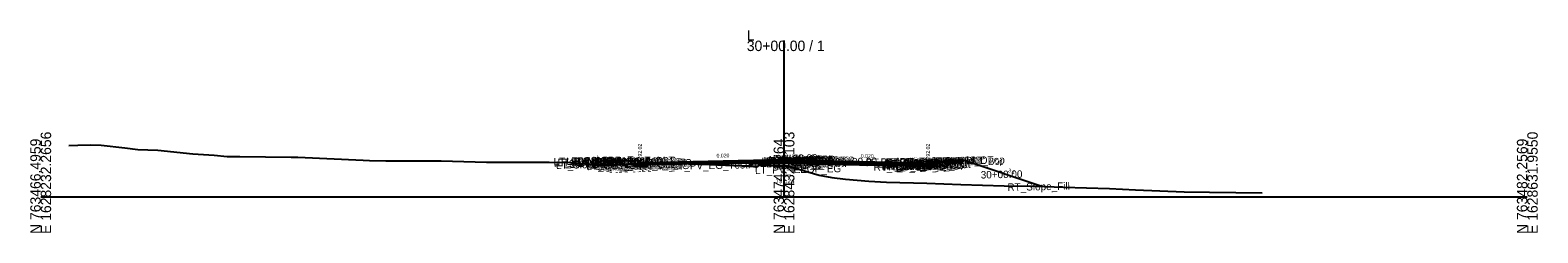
# Model space of a CAD drawing. Extents: x -26 to 4403, y -510 to 9556.
# Drawn here: x 1997.2 to 2402.8, y -9.7 to 44.7 of the extents above; entities that cross this region are included whole.
import ezdxf

# ---------------------------------------------------------------- set-up
doc = ezdxf.new("R2010")
doc.units = 0
for name, color, linetype in [('Default', 7, 'Continuous'), ('Exist CMT Pavement', 7, 'Continuous'), ('Exist Cross Section Cell', 7, 'Continuous'), ('Exist XS Center Line Elevation Label', 7, 'Continuous'), ('Exist XS Ground Line', 7, 'Continuous'), ('Prop CMT Conc Surface', 7, 'Continuous'), ('Prop CMT Concrete Structures', 7, 'Continuous'), ('Prop CMT Pvmt Course 1', 7, 'Continuous'), ('Prop CMT Pvmt Course 1 CG', 7, 'Continuous'), ('Prop CMT Pvmt Course 1 Wedge', 7, 'Continuous'), ('Prop CMT Pvmt Course 2', 7, 'Continuous'), ('Prop CMT Pvmt Course 2 Wedge', 7, 'Continuous'), ('Prop CMT Pvmt Course 3', 7, 'Continuous'), ('Prop CMT Pvmt Course 3 Wedge', 7, 'Continuous'), ('Prop CMT Pvmt Surface', 7, 'Continuous'), ('Prop CMT Pvmt Wedge Surface 1', 7, 'Continuous'), ('Prop CMT Pvmt Wedge Surface 2', 7, 'Continuous'), ('Prop CMT Pvmt Wedge Surface 3', 7, 'Continuous'), ('Prop CMT Slope Grass', 7, 'Continuous'), ('Prop CMT Subgrade Earthwork', 7, 'Continuous'), ('Prop XS Hydro Elevations', 7, 'Continuous'), ('Prop XS SE Text', 7, 'Continuous'), ('Prop XS Side Slope Text', 7, 'Continuous'), ('Scratch_Level_0', 7, 'Continuous')]:
    doc.layers.add(name, color=color, linetype=linetype)

msp = doc.modelspace()

# ---------------------------------------------------------------- linework, layer by layer
at = {"layer": 'Exist CMT Pavement'}
msp.add_lwpolyline([(2163.27, 8.89), (2165.6, 8.9), (2171.45, 8.94), (2179.91, 8.63), (2190.78, 8.23)], dxfattribs=at)
at = {"layer": 'Exist Cross Section Cell'}
for p, q in [((2200, 0), (2200, 41.94)), ((2000, 0), (2200, 0)), ((2200, 0), (2400, 0))]:
    msp.add_line(p, q, dxfattribs=at)
at = {"layer": 'Exist XS Ground Line'}
msp.add_lwpolyline([(2007.54, 13.74), (2010, 13.87), (2013.27, 13.98), (2016.24, 13.83), (2022.59, 13.11), (2026.12, 12.73), (2028.83, 12.63), (2031.47, 12.5), (2040.91, 11.51), (2046.71, 11.14), (2050.14, 10.82), (2053.55, 10.82), (2067.42, 10.65), (2068.48, 10.61), (2069.17, 10.63), (2086.73, 9.82), (2088.47, 9.74), (2092.85, 9.65), (2107.79, 9.66), (2119.91, 9.32), (2127.57, 9.28), (2136.85, 9.3), (2142.39, 9.21), (2146.29, 8.83), (2149.18, 8.58), (2149.55, 8.52), (2150.04, 8.48), (2156.17, 8.69), (2160.96, 8.87), (2165.6, 8.9), (2171.45, 8.94), (2179.91, 8.63), (2190.78, 8.23), (2192.8, 8.06), (2193.33, 8.48), (2198.8, 8.26), (2200, 8.24), (2201.17, 8.22), (2204.26, 7.3), (2209.45, 5.8), (2212.85, 5.2), (2216.58, 4.7), (2222.81, 4.21), (2227.54, 3.95), (2238.45, 3.61), (2247.56, 3.26), (2259.28, 2.96), (2267.57, 2.81), (2275.23, 2.58), (2287.59, 2.19), (2294.54, 1.89), (2307.66, 1.3), (2314.51, 1.2), (2328.67, 1.08)], dxfattribs=at)
at = {"layer": 'Prop CMT Conc Surface'}
for points in [[(2156.75, 9.61), (2151.75, 9.71)], [(2161.25, 9.02), (2161.25, 9.52), (2160.75, 9.52)], [(2163.25, 9.14), (2161.25, 9.02)], [(2236.75, 9.14), (2238.75, 9.02)], [(2238.75, 9.02), (2238.75, 9.52), (2239.25, 9.52)], [(2243.25, 9.61), (2248.25, 9.71)]]:
    msp.add_lwpolyline(points, dxfattribs=at)
at = {"layer": 'Prop CMT Concrete Structures'}
for points in [[(2151.75, 9.38), (2151.75, 9.71)], [(2151.75, 9.71), (2156.75, 9.61)], [(2156.75, 9.28), (2151.75, 9.38)], [(2156.75, 9.61), (2156.75, 9.28)], [(2163.25, 9.14), (2161.25, 9.02), (2161.25, 9.52), (2160.75, 9.52)], [(2160.75, 9.52), (2160.75, 8.51), (2163.25, 8.56)], [(2163.25, 8.56), (2163.25, 9.14)], [(2208, 9.72), (2207.99, 9.88), (2207.24, 10.14), (2206, 10.4), (2204.76, 10.38), (2204.01, 10.12), (2204, 9.96)], [(2204, 9.96), (2208, 9.72)], [(2236.75, 9.14), (2238.75, 9.02), (2238.75, 9.52), (2239.25, 9.52)], [(2239.25, 9.52), (2239.25, 8.51), (2236.75, 8.56)], [(2236.75, 8.56), (2236.75, 9.14)], [(2248.25, 9.71), (2243.25, 9.61)], [(2243.25, 9.61), (2243.25, 9.28)], [(2243.25, 9.28), (2248.25, 9.38)], [(2248.25, 9.38), (2248.25, 9.71)]]:
    msp.add_lwpolyline(points, dxfattribs=at)
at = {"layer": 'Prop CMT Pvmt Course 1'}
for points in [[(2204, 9.96), (2163.25, 9.14)], [(2163.25, 9.02), (2204, 9.83)], [(2163.25, 9.14), (2163.25, 8.89), (2163.25, 8.89), (2163.25, 9.02)], [(2204, 9.96), (2208, 9.72)], [(2204, 9.71), (2204, 9.96)], [(2204, 9.71), (2204, 9.96)], [(2204, 9.83), (2204, 9.71), (2204, 9.71)], [(2208, 9.47), (2204, 9.71)], [(2208, 9.72), (2208, 9.47)], [(2208, 9.72), (2236.75, 9.14)], [(2208, 9.47), (2208, 9.72)], [(2236.75, 8.89), (2208, 9.47)], [(2236.75, 9.14), (2236.75, 8.89)]]:
    msp.add_lwpolyline(points, dxfattribs=at)
msp.add_lwpolyline([(2208, 9.47), (2208, 9.59), (2208, 9.59), (2208, 9.47)], close=True, dxfattribs=at)
at = {"layer": 'Prop CMT Pvmt Course 1 CG'}
for points in [[(2163.25, 8.56), (2160.25, 8.5), (2159.91, 8.16)], [(2159.91, 8.16), (2163.25, 8.23)], [(2163.25, 8.23), (2163.25, 8.56)], [(2236.75, 8.56), (2239.75, 8.5), (2240.09, 8.16)], [(2236.75, 8.23), (2236.75, 8.56)], [(2240.09, 8.16), (2236.75, 8.23)]]:
    msp.add_lwpolyline(points, dxfattribs=at)
at = {"layer": 'Prop CMT Pvmt Course 1 Wedge'}
for points in [[(2163.25, 9.02), (2165.6, 9.07), (2171.45, 9.18), (2179.91, 9.35), (2190.78, 9.57), (2192.58, 9.6), (2192.8, 9.61), (2192.86, 9.61), (2193.33, 9.62), (2198.8, 9.73), (2201.17, 9.78), (2204, 9.83)], [(2204, 9.71), (2201.17, 9.65), (2198.8, 9.6), (2193.33, 9.49), (2192.86, 9.49), (2192.8, 9.48), (2192.58, 9.48), (2190.78, 9.44), (2179.91, 9.23), (2171.45, 9.06), (2165.6, 8.94), (2163.25, 8.89)], [(2163.25, 8.89), (2163.25, 9.02)], [(2204, 9.83), (2204, 9.71)]]:
    msp.add_lwpolyline(points, dxfattribs=at)
at = {"layer": 'Prop CMT Pvmt Course 2'}
for points in [[(2163.25, 8.56), (2163.25, 8.56), (2163.25, 8.89), (2163.25, 8.89)], [(2163.25, 8.89), (2163.25, 8.56)], [(2204, 9.71), (2208, 9.47)], [(2204, 9.37), (2204, 9.71)], [(2208, 9.14), (2204, 9.37)], [(2208, 9.47), (2208, 9.14)], [(2208, 9.14), (2208, 9.47)], [(2208, 9.47), (2236.75, 8.89)], [(2236.75, 8.56), (2208, 9.14)], [(2236.75, 8.89), (2236.75, 8.56)]]:
    msp.add_lwpolyline(points, dxfattribs=at)
at = {"layer": 'Prop CMT Pvmt Course 2 Wedge'}
for points in [[(2163.25, 8.89), (2165.6, 8.94), (2171.45, 9.06), (2179.91, 9.23), (2190.78, 9.44), (2192.58, 9.48), (2192.8, 9.48), (2192.86, 9.49), (2193.33, 9.49), (2198.8, 9.6), (2201.17, 9.65), (2204, 9.71)], [(2204, 9.37), (2201.17, 9.32), (2198.8, 9.27), (2193.33, 9.16), (2192.86, 9.15), (2192.8, 9.15), (2192.58, 9.15), (2190.78, 9.11), (2179.91, 8.89), (2175.21, 8.8), (2171.45, 8.94), (2165.6, 8.9), (2163.25, 8.89)], [(2163.25, 8.89), (2163.25, 8.89)], [(2204, 9.71), (2204, 9.37)]]:
    msp.add_lwpolyline(points, dxfattribs=at)
at = {"layer": 'Prop CMT Pvmt Course 3'}
for points in [[(2163.25, 8.56), (2163.25, 8.56), (2163.25, 8.23), (2163.25, 8.23)], [(2163.25, 8.23), (2163.25, 8.56)], [(2204, 9.37), (2208, 9.14)], [(2204, 9.04), (2204, 9.37)], [(2208, 8.8), (2204, 9.04)], [(2208, 9.14), (2208, 8.8)], [(2208, 9.14), (2236.75, 8.56)], [(2208, 8.8), (2208, 9.14)], [(2236.75, 8.23), (2208, 8.8)], [(2236.75, 8.56), (2236.75, 8.23)]]:
    msp.add_lwpolyline(points, dxfattribs=at)
at = {"layer": 'Prop CMT Pvmt Course 3 Wedge'}
for points in [[(2175.2, 8.8), (2179.91, 8.89)], [(2204, 7.37), (2201.17, 8.22), (2198.8, 8.26), (2193.33, 8.48), (2192.86, 8.1), (2192.8, 8.06), (2192.58, 8.08), (2190.78, 8.23), (2179.91, 8.63), (2175.2, 8.8)], [(2179.91, 8.89), (2190.78, 9.11), (2192.58, 9.15), (2192.8, 9.15), (2192.86, 9.15), (2193.33, 9.16), (2198.8, 9.27), (2201.17, 9.32), (2204, 9.37)]]:
    msp.add_lwpolyline(points, dxfattribs=at)
at = {"layer": 'Prop CMT Pvmt Surface'}
for points in [[(2204, 9.96), (2163.25, 9.14)], [(2204, 9.96), (2208, 9.72)], [(2208, 9.72), (2236.75, 9.14)]]:
    msp.add_lwpolyline(points, dxfattribs=at)
at = {"layer": 'Prop CMT Pvmt Wedge Surface 1'}
for points in [[(2204, 9.83), (2163.25, 9.02)], [(2163.25, 8.89), (2163.25, 9.14)], [(2163.25, 9.02), (2163.25, 8.89), (2163.25, 8.89)], [(2204, 9.96), (2204, 9.71), (2204, 9.71), (2204, 9.83)]]:
    msp.add_lwpolyline(points, dxfattribs=at)
at = {"layer": 'Prop CMT Pvmt Wedge Surface 2'}
for points in [[(2204, 9.71), (2163.25, 8.89)], [(2163.25, 8.89), (2163.25, 9.14)], [(2204, 9.96), (2204, 9.71)]]:
    msp.add_lwpolyline(points, dxfattribs=at)
at = {"layer": 'Prop CMT Pvmt Wedge Surface 3'}
for points in [[(2204, 9.37), (2163.25, 8.56)], [(2163.25, 8.56), (2163.25, 9.14)], [(2204, 9.96), (2204, 9.37)]]:
    msp.add_lwpolyline(points, dxfattribs=at)
at = {"layer": 'Prop CMT Slope Grass'}
for points in [[(2160.75, 9.52), (2151.25, 9.71), (2148.12, 8.67)], [(2239.25, 9.52), (2248.25, 9.7)], [(2248.25, 9.7), (2248.75, 9.71), (2269.65, 2.75)]]:
    msp.add_lwpolyline(points, dxfattribs=at)
at = {"layer": 'Prop CMT Subgrade Earthwork'}
for points in [[(2163.25, 8.23), (2159.91, 8.16), (2158.5, 9.57)], [(2163.25, 8.23), (2163.27, 8.89)], [(2163.25, 8.23), (2163.25, 8.23)], [(2204, 9.04), (2201.17, 8.98), (2198.8, 8.94), (2193.33, 8.83), (2192.86, 8.82), (2192.8, 8.82), (2192.58, 8.81), (2190.78, 8.78)], [(2190.78, 8.78), (2190.78, 8.23)], [(2204, 9.04), (2208, 8.8)], [(2208, 8.8), (2236.75, 8.23)], [(2236.75, 8.23), (2240.09, 8.16), (2241.5, 9.57)]]:
    msp.add_lwpolyline(points, dxfattribs=at)

# ---------------------------------------------------------------- texts
at = {"layer": 'Default'}
msp.add_text('-', height=0.0001, dxfattribs=at).set_placement((2000, 0))
at = {"layer": 'Exist Cross Section Cell'}
for s, p in [('L', (2190, 41.94)), ('30+00.00 / 1', (2190, 39.14))]:
    msp.add_text(s, height=2.8, dxfattribs=at).set_placement(p)
for s, p in [('E 1628232.2656', (2002.8, -10)), ('E 1628432.1103', (2202.8, -10)), ('E 1628631.9550', (2402.8, -10)), ('N 763466.4959', (2000, -10)), ('N 763474.3764', (2200, -10)), ('N 763482.2569', (2400, -10))]:
    msp.add_text(s, height=2.8, rotation=90, dxfattribs=at).set_placement(p)
at = {"layer": 'Exist XS Center Line Elevation Label'}
msp.add_text('791.24', height=1.2, dxfattribs=at).set_placement((2197.72, 3.64))
at = {"layer": 'Prop XS Hydro Elevations'}
for p in [(2161.75, 10.02), (2239.25, 10.02)]:
    msp.add_text('792.02', height=1, rotation=90, dxfattribs=at).set_placement(p)
at = {"layer": 'Prop XS SE Text'}
for rotation, p in [(1.1458, (2181.86, 10.52)), (358.8542, (2220.65, 10.47))]:
    msp.add_text('0.020', height=1, rotation=rotation, dxfattribs=at).set_placement(p)
at = {"layer": 'Prop XS Side Slope Text'}
for rotation, p in [(18.4324, (2148.7, 9.65)), (341.5647, (2260.18, 6.69))]:
    msp.add_text('3:1', height=1, rotation=rotation, dxfattribs=at).set_placement(p)
at = {"layer": 'Scratch_Level_0'}
for s, p in [('LT_SDWK_Out_Top', (2138.01, 8.44)), ('LT_SDWK_Out_Bot', (2138.04, 8.11)), ('LT_Slope_Fill', (2138.66, 7.48)), ('LT_Sub_Trench_Out_DLT', (2139.09, 8.18)), ('LT_CSLP_Pnt', (2141.45, 8.52)), ('30+00.00', (2142.22, 7.86)), ('30+00.00', (2144.69, 8.57)), ('LT_SDWK_In_Top', (2144.63, 8.37)), ('LT_SDWK_In_Bot', (2144.66, 8.04)), ('LT_CG1_Shelf_Out', (2146.82, 7.23)), ('LT_PV_Sub_Tie_Out', (2148.23, 7.58)), ('LT_CG_Top_Face', (2148.53, 8.27)), ('LT_CG_Top_BOC', (2149.06, 8.29)), ('LT_CG_Bot_BOC', (2149.09, 7.28)), ('LT_CG_Top_Gut', (2149.51, 7.79)), ('LT_Sub_OEOP', (2150.04, 6.96)), ('LT_Sub_OEOT_CG', (2150.64, 6.97)), ('LT_PV_OEEOP_EG', (2150.82, 7.64)), ('LT_Sub_OEEOP', (2152.48, 7.01)), ('LT_PV2_OEEOP', (2152.58, 7.68)), ('LT_PV3_OEEOP', (2152.58, 7.35)), ('30+00.00', (2152.96, 8.4)), ('LT_PV1_OEEOP', (2153.15, 7.82)), ('LT_CG_Bot_IE', (2153.19, 7.36)), ('LT_Sub_OEOT', (2153.35, 7.03)), ('LT_PV2_OEOT', (2153.45, 7.7)), ('LT_PV3_OEOT', (2153.45, 7.36)), ('LT_PV1_OEOT', (2154.01, 7.96)), ('30+00.00', (2155.46, 7.95)), ('LT_PV_EG_TestPt', (2170.06, 7.22)), ('LT_PV_IEEOP_EG', (2192.21, 6.14)), ('LT_PV2_IEEOP', (2193.97, 8.51)), ('LT_PV3_IEEOP', (2193.97, 8.17)), ('LT_PV1_IEEOP', (2194.54, 8.64)), ('LT_PV2_PGL1', (2194.9, 8.53)), ('LT_PV3_PGL1', (2194.9, 8.19)), ('LT_PV2_PGL', (2195.23, 8.53)), ('LT_PV3_PGL', (2195.23, 8.2)), ('LT_PV4_PGL', (2195.23, 7.87)), ('LT_PV1_PGL', (2195.8, 8.79)), ('MI_Face In', (2195.92, 8.96)), ('RT_Sub_OEEOP', (2197.19, 7.58)), ('RT_PV2_OEEOP', (2197.28, 8.25)), ('RT_PV3_OEEOP', (2197.28, 7.92)), ('MI_Top In', (2197.63, 9.23)), ('30+00.00', (2197.84, 9.23)), ('RT_PV1_OEEOP', (2197.85, 8.39)), ('RT_PV2_IEEOP', (2197.93, 8.27)), ('MI_Face Out', (2198.28, 8.69)), ('MI_Top Out', (2198.49, 8.96)), ('RT_PV1_IEEOP', (2198.49, 8.4)), ('RT_PV2_PGL1', (2198.86, 8.28)), ('RT_PV3_PGL1', (2198.86, 7.95)), ('MI_Crown', (2199.09, 9.26)), ('RT_PV2_PGL', (2199.19, 8.29)), ('RT_PV4_PGL', (2199.19, 7.62)), ('MI_Bot Out', (2199.28, 8.54)), ('RT_PV1_PGL', (2199.75, 8.55)), ('30+00.00', (2200.77, 8.86)), ('30+00.00', (2201.1, 8.68)), ('30+00.00', (2213.8, 8.33)), ('RT_Sub_Trench_Out_DLT', (2222.04, 8.18)), ('RT_Sub_OEOT_CG', (2224.1, 6.97)), ('RT_CG_Top_Face', (2225.99, 8.27)), ('RT_CG1_Shelf_Out', (2226.28, 7.23)), ('RT_CG_Bot_IE', (2226.64, 7.36)), ('RT_Sub_OEOT', (2226.8, 7.03)), ('RT_PV2_OEOT', (2226.9, 7.7)), ('RT_PV3_OEOT', (2226.9, 7.36)), ('RT_CG_Top_Gut', (2226.96, 7.79)), ('RT_PV1_OEOT', (2227.47, 7.96)), ('RT_CG_Top_BOC', (2227.51, 8.29)), ('RT_CG_Bot_BOC', (2227.54, 7.28)), ('RT_Sub_OEOP', (2230.17, 6.96)), ('RT_SDWK_In_Top', (2231.08, 8.37)), ('RT_SDWK_In_Bot', (2231.12, 8.04)), ('30+00.00', (2232.42, 8.39)), ('RT_SDWK_Out_Top', (2234.46, 8.44)), ('RT_SDWK_Out_Bot', (2234.49, 8.1)), ('RT_Shld_O', (2240.81, 8.55)), ('CSLP_Pnt', (2241.64, 8.57)), ('30+00.00', (2241.66, 8.57)), ('30+00.00', (2252.95, 4.88)), ('RT_Slope_Fill', (2260.14, 1.56))]:
    msp.add_text(s, height=2, rotation=1.1458, dxfattribs=at).set_placement(p)

doc.saveas('drawing.dxf')
